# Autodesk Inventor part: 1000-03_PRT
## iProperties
Created: 2007-03
Part Number: 1000-03_PRT
Document SubType Name: Modeling
Designer: Andy Moles
Material: Steel
Mass: 0.484358 g
Surface Area: 2.54827 cm^2
Volume: 0.0617016 cm^3
Density: 7.85 g/cm^3
Author: Andy Moles
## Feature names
1. Base1
